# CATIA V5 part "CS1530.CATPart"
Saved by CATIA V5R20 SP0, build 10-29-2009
Part number: CS1530
Revision: 5
Definition: design
Nomenclature: CS1530
Source: made
Description: NOT SPECIFIED
Bounding box of the stored display mesh (mm): x -29 to 29, y -29 to 29, z -55 to 15
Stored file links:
  C:\Users\Raffaele\Desktop\3D X SITO CF\BOLEX\20-TILTED COLUMN SUPPORT\CS1530.CATPart
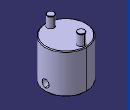
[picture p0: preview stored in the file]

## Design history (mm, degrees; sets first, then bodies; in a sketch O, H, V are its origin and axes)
Body1 "MANIFOLD_SOLID_BREP #715" (main body)
  Solid1: solid without history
